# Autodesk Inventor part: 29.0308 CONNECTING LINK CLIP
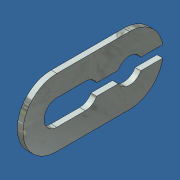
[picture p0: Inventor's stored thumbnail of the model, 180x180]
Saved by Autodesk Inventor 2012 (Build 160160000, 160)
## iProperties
Created: 2013-10
Part Number: 29.0308 CONNECTING LINK CLIP
Material: Steel
Document SubType Name: Modeling
Designer: Admin
Density: 7.85 g/cm^3
Mass: 1.50409 g
Surface Area: 4.9043 cm^2
Volume: 0.191604 cm^3
Author: Admin
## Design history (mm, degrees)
node "Product1"
node "Base1"
body "Solid1"
